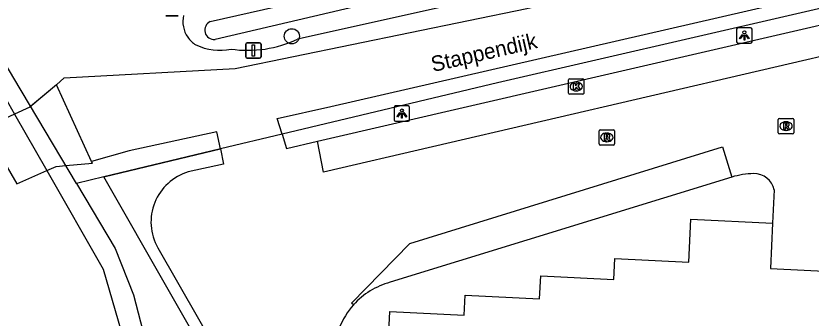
# Model space of a CAD drawing. Extents: x 161094 to 161705, y 379509 to 380907.
# Drawn here: x 161197.2 to 161248.7, y 379714.9 to 379734.5 of the extents above; entities that cross this region are included whole.
import ezdxf

# ---------------------------------------------------------------- set-up
doc = ezdxf.new("R2010")
doc.units = 0
for name, color, linetype in [('IMGEO_Afsluitpaal', 7, 'Continuous'), ('IMGEO_Boom', 7, 'Continuous'), ('IMGEO_Dek', 7, 'Continuous'), ('IMGEO_Fietspad_gesloten', 7, 'Continuous'), ('IMGEO_Groenvoorziening', 7, 'Continuous'), ('IMGEO_Hek', 7, 'Continuous'), ('IMGEO_Kolk', 7, 'Continuous'), ('IMGEO_Lichtpunt', 7, 'Continuous'), ('IMGEO_Openbare_ruimte_label', 7, 'Continuous'), ('IMGEO_Pand', 7, 'Continuous'), ('IMGEO_Parkeervlak_gesloten', 7, 'Continuous'), ('IMGEO_Rijbaan_lokaal_gesloten', 7, 'Continuous'), ('IMGEO_Rioolput', 7, 'Continuous'), ('IMGEO_Verkeersbordpaal', 7, 'Continuous'), ('IMGEO_Waterloop', 7, 'Continuous')]:
    doc.layers.add(name, color=color, linetype=linetype)

msp = doc.modelspace()

# ---------------------------------------------------------------- linework, layer by layer
at = {"layer": 'IMGEO_Afsluitpaal'}
for p, q in [((161207.736, 379734.468), (161206.946, 379734.468)), ((161206.946, 379734.468), (161207.736, 379734.468))]:
    msp.add_line(p, q, dxfattribs=at)
at = {"layer": 'IMGEO_Boom'}
msp.add_circle((161215.101, 379733.152), 0.489, dxfattribs=at)
at = {"layer": 'IMGEO_Dek'}
msp.add_lwpolyline([(161197.31, 379723.614), (161199.237, 379724.462), (161199.849, 379724.731), (161200.473, 379724.788), (161202.193, 379724.943), (161202.141, 379725.056), (161199.88, 379730.004), (161198.199, 379728.614), (161198.153, 379728.576), (161197.144, 379728.113), (161195.19, 379727.216)], close=True, dxfattribs=at)
at = {"layer": 'IMGEO_Fietspad_gesloten'}
for points in [[(161210.481, 379725.863), (161210.245, 379726.978), (161204.585, 379725.735), (161202.141, 379725.056), (161199.88, 379730.004), (161200.37, 379730.456), (161211.43, 379731.076), (161230.315, 379734.955), (161294.533, 379750), (161302.182, 379751.792), (161318.2, 379756.091), (161323.089, 379757.248), (161325.661, 379758.067), (161372.453, 379776.813), (161386.356, 379782.534), (161407.443, 379791.212), (161432.033, 379800.962), (161436.35, 379802.535), (161437.461, 379802.835), (161438.334, 379803.07)], [(161214.473, 379726.815), (161214.16, 379727.839), (161217.63, 379728.601), (161261.386, 379738.685), (161308.111, 379750), (161320.623, 379753.03), (161330.613, 379756.284), (161333.8, 379757.687), (161368.776, 379771.487), (161387.909, 379779.27), (161415.666, 379790.561)]]:
    msp.add_lwpolyline(points, dxfattribs=at)
at = {"layer": 'IMGEO_Groenvoorziening'}
for points in [[(161321.194, 379761.932), (161383.047, 379787.15), (161437.336, 379808.629), (161438.26, 379805.933), (161414.978, 379796.508), (161345.338, 379767.612), (161322.581, 379758.384), (161307.399, 379754.371), (161244.228, 379739.369), (161215.479, 379732.972)], [(161415.916, 379790.022), (161359.784, 379767.053), (161334.748, 379757.161), (161323.449, 379753.122), (161314.492, 379750.449), (161260.228, 379737.49), (161228.423, 379730.143), (161214.473, 379726.815)], [(161201.159, 379723.634), (161197.105, 379730.453), (161194.335, 379735.113), (161189.385, 379745.645), (161184.615, 379755.126), (161180.807, 379761.477)], [(161202.937, 379724.063), (161210.481, 379725.863)], [(161202.937, 379724.063), (161201.159, 379723.634)], [(161224.271, 379686.726), (161202.937, 379724.063)], [(161201.159, 379723.634), (161203.662, 379719.423), (161204.854, 379716.43), (161205.758, 379712.932), (161206.301, 379709.758), (161206.372, 379708.219)]]:
    msp.add_lwpolyline(points, dxfattribs=at)
for centre, radius, start, end in [((161209.849, 379734.112), 1.8, 167.4846, 214.3982), ((161209.848, 379734.116), 1.801, 214.5145, 237.8238), ((161210.452, 379736.058), 3.803, 245.735, 280.8512), ((161212.257, 379739.735), 7.491, 261.6448, 295.4778)]:
    msp.add_arc(centre, radius, start, end, dxfattribs=at)
at = {"layer": 'IMGEO_Hek'}
for points in [[(161415.916, 379790.022), (161359.784, 379767.053), (161334.748, 379757.161), (161323.449, 379753.122), (161314.492, 379750.449), (161260.228, 379737.49), (161228.423, 379730.143), (161214.473, 379726.815)], [(161199.88, 379730.004), (161198.153, 379728.576), (161197.144, 379728.113), (161195.19, 379727.216)], [(161214.473, 379726.815), (161210.481, 379725.863)], [(161210.481, 379725.863), (161202.937, 379724.063)], [(161197.31, 379723.614), (161199.237, 379724.462), (161199.849, 379724.731), (161200.473, 379724.788), (161202.193, 379724.943)], [(161224.271, 379686.726), (161202.937, 379724.063)]]:
    msp.add_lwpolyline(points, dxfattribs=at)
at = {"layer": 'IMGEO_Kolk'}
for p, q in [((161233.011, 379729.473), (161233.011, 379730.325)), ((161233.086, 379730.399), (161233.938, 379730.399)), ((161233.499, 379730.179), (161233.524, 379730.179)), ((161234.012, 379730.325), (161234.012, 379729.473)), ((161233.522, 379729.619), (161233.497, 379729.619)), ((161233.938, 379729.399), (161233.086, 379729.399))]:
    msp.add_line(p, q, dxfattribs=at)
for points in [[(161233.011, 379729.473), (161233.011, 379730.325)], [(161233.086, 379730.399), (161233.938, 379730.399)], [(161233.332, 379730.099), (161233.455, 379730.099), (161233.455, 379729.948), (161233.585, 379730.099), (161233.749, 379730.099), (161233.603, 379729.948), (161233.756, 379729.699), (161233.604, 379729.699), (161233.519, 379729.863), (161233.455, 379729.796), (161233.455, 379729.699), (161233.332, 379729.699), (161233.332, 379730.099)], [(161234.012, 379730.325), (161234.012, 379729.473)], [(161233.938, 379729.399), (161233.086, 379729.399)]]:
    msp.add_lwpolyline(points, dxfattribs=at)
for centre, start, end in [((161233.088, 379730.323), 91.552, 178.448), ((161233.088, 379730.323), 91.552, 178.448), ((161233.936, 379730.323), 1.552, 88.448), ((161233.936, 379730.323), 1.552, 88.448), ((161233.088, 379729.475), 181.552, 268.448), ((161233.088, 379729.475), 181.552, 268.448), ((161233.936, 379729.475), 271.552, 358.448), ((161233.936, 379729.475), 271.552, 358.448)]:
    msp.add_arc(centre, 0.0765, start, end, dxfattribs=at)
for centre, major_axis, ratio, start_param, end_param in [((161233.498, 379729.899), (-0.387, 0.002), 0.722429, 4.712389, 7.853982), ((161233.523, 379729.899), (-0.39, 0.002), 0.717154, 1.570796, 4.712389)]:
    msp.add_ellipse(centre, major_axis=major_axis, ratio=ratio, start_param=start_param, end_param=end_param, dxfattribs=at)
at = {"layer": 'IMGEO_Lichtpunt'}
for p, q in [((161243.893, 379733.61), (161243.893, 379732.803)), ((161243.893, 379733.61), (161243.893, 379732.803)), ((161244.795, 379733.705), (161243.987, 379733.705)), ((161244.795, 379733.705), (161243.987, 379733.705)), ((161244.889, 379732.803), (161244.889, 379733.61)), ((161244.889, 379732.803), (161244.889, 379733.61)), ((161243.987, 379732.709), (161244.795, 379732.709)), ((161243.987, 379732.709), (161244.795, 379732.709)), ((161221.727, 379728.553), (161221.727, 379727.746)), ((161221.727, 379728.553), (161221.727, 379727.746)), ((161222.629, 379728.648), (161221.821, 379728.648)), ((161222.629, 379728.648), (161221.821, 379728.648)), ((161222.723, 379727.746), (161222.723, 379728.553)), ((161222.723, 379727.746), (161222.723, 379728.553)), ((161221.821, 379727.652), (161222.629, 379727.652)), ((161221.821, 379727.652), (161222.629, 379727.652))]:
    msp.add_line(p, q, dxfattribs=at)
for points in [[(161244.267, 379733.274), (161244.306, 379733.246), (161244.118, 379732.984), (161244.08, 379733.011), (161244.267, 379733.274)], [(161244.369, 379733.226), (161244.416, 379733.226), (161244.416, 379732.904), (161244.369, 379732.904), (161244.369, 379733.226)], [(161244.479, 379733.246), (161244.517, 379733.273), (161244.704, 379733.011), (161244.665, 379732.983), (161244.479, 379733.246)], [(161222.101, 379728.217), (161222.14, 379728.189), (161221.952, 379727.927), (161221.914, 379727.954), (161222.101, 379728.217)], [(161222.203, 379728.169), (161222.25, 379728.169), (161222.25, 379727.847), (161222.203, 379727.847), (161222.203, 379728.169)], [(161222.313, 379728.189), (161222.351, 379728.216), (161222.538, 379727.954), (161222.499, 379727.926), (161222.313, 379728.189)]]:
    msp.add_lwpolyline(points, dxfattribs=at)
for centre in [(161244.392, 379733.408), (161222.226, 379728.351)]:
    msp.add_circle(centre, 0.0994, dxfattribs=at)
for centre, start, end in [((161243.987, 379733.61), 90, 180), ((161243.987, 379733.61), 90, 180), ((161244.795, 379733.61), 0, 90), ((161244.795, 379733.61), 0, 90), ((161243.987, 379732.803), 180, 270), ((161243.987, 379732.803), 180, 270), ((161244.795, 379732.803), 270, 0), ((161244.795, 379732.803), 270, 360), ((161221.821, 379728.553), 90, 180), ((161221.821, 379728.553), 90, 180), ((161222.629, 379728.553), 0, 90), ((161222.629, 379728.553), 0, 90), ((161221.821, 379727.746), 180, 270), ((161221.821, 379727.746), 180, 270), ((161222.629, 379727.746), 270, 0), ((161222.629, 379727.746), 270, 360)]:
    msp.add_arc(centre, 0.0946, start, end, dxfattribs=at)
at = {"layer": 'IMGEO_Pand'}
for points in [[(161246.219, 379721.063), (161246.076, 379718.139), (161250.433, 379717.926), (161250.668, 379722.709)], [(161221.202, 379710.583), (161221.435, 379715.343), (161226.263, 379715.106), (161226.326, 379716.404), (161231.137, 379716.169), (161231.21, 379717.664), (161235.949, 379717.432), (161236.015, 379718.779), (161240.798, 379718.545), (161240.934, 379721.322), (161246.219, 379721.063)]]:
    msp.add_lwpolyline(points, dxfattribs=at)
at = {"layer": 'IMGEO_Parkeervlak_gesloten'}
for points in [[(161216.77, 379726.358), (161281.548, 379741.341)], [(161243.578, 379724.047), (161221.468, 379717.239)]]:
    msp.add_lwpolyline(points, dxfattribs=at)
msp.add_arc((161222.749, 379712.493), 4.916, 105.1074, 138.0537, dxfattribs=at)
at = {"layer": 'IMGEO_Rijbaan_lokaal_gesloten'}
for points in [[(161281.548, 379741.341), (161281.952, 379739.475), (161252.424, 379732.547), (161217.161, 379724.368), (161216.77, 379726.358)], [(161214.473, 379726.815), (161210.481, 379725.863)], [(161214.473, 379726.815), (161214.755, 379725.892), (161216.77, 379726.358)], [(161210.481, 379725.863), (161210.689, 379724.879), (161208.4, 379724.379)], [(161219.093, 379715.779), (161218.965, 379715.895), (161222.736, 379719.759), (161242.968, 379725.996), (161243.578, 379724.047)], [(161246.325, 379723.213), (161246.219, 379721.063)], [(161206.424, 379719.47), (161218.401, 379698.575), (161236.659, 379665.622)]]:
    msp.add_lwpolyline(points, dxfattribs=at)
for centre, radius, start, end in [((161209.375, 379721.134), 3.388, 106.7284, 209.4194), ((161245.164, 379718.582), 5.691, 91.7141, 106.1855), ((161245.027, 379722.945), 1.326, 11.6765, 91.4146), ((161222.756, 379712.5), 4.917, 138.1622, 179.1438)]:
    msp.add_arc(centre, radius, start, end, dxfattribs=at)
at = {"layer": 'IMGEO_Rioolput'}
for p, q in [((161246.587, 379726.917), (161246.587, 379727.769)), ((161246.662, 379727.843), (161247.514, 379727.843)), ((161247.075, 379727.623), (161247.1, 379727.623)), ((161247.588, 379727.769), (161247.588, 379726.917)), ((161234.99, 379726.185), (161234.99, 379727.037)), ((161235.065, 379727.111), (161235.917, 379727.111)), ((161235.478, 379726.891), (161235.503, 379726.891)), ((161235.991, 379727.037), (161235.991, 379726.185)), ((161247.098, 379727.063), (161247.073, 379727.063)), ((161247.514, 379726.843), (161246.662, 379726.843)), ((161235.917, 379726.111), (161235.065, 379726.111)), ((161235.501, 379726.331), (161235.476, 379726.331))]:
    msp.add_line(p, q, dxfattribs=at)
for points in [[(161246.587, 379726.917), (161246.587, 379727.769)], [(161246.662, 379727.843), (161247.514, 379727.843)], [(161247.176, 379727.541), (161246.924, 379727.543), (161246.924, 379727.143)], [(161247.102, 379727.462), (161247.048, 379727.462), (161247.048, 379727.381)], [(161247.588, 379727.769), (161247.588, 379726.917)], [(161234.99, 379726.185), (161234.99, 379727.037)], [(161235.065, 379727.111), (161235.917, 379727.111)], [(161235.991, 379727.037), (161235.991, 379726.185)], [(161246.924, 379727.143), (161247.048, 379727.143), (161247.048, 379727.305), (161247.059, 379727.305)], [(161247.048, 379727.381), (161247.1, 379727.381)], [(161247.106, 379727.276), (161247.177, 379727.143), (161247.317, 379727.143), (161247.252, 379727.269)], [(161235.579, 379726.809), (161235.327, 379726.811), (161235.327, 379726.411)], [(161235.327, 379726.411), (161235.451, 379726.411), (161235.451, 379726.573), (161235.462, 379726.573)], [(161235.505, 379726.73), (161235.451, 379726.73), (161235.451, 379726.649)], [(161235.451, 379726.649), (161235.503, 379726.649)], [(161235.509, 379726.544), (161235.58, 379726.411), (161235.72, 379726.411), (161235.655, 379726.537)], [(161247.514, 379726.843), (161246.662, 379726.843)], [(161235.917, 379726.111), (161235.065, 379726.111)]]:
    msp.add_lwpolyline(points, dxfattribs=at)
for centre, radius, start, end in [((161246.664, 379727.767), 0.0765, 91.552, 178.448), ((161246.664, 379727.767), 0.0765, 91.552, 178.448), ((161247.084, 379727.57), 0.19, 274.7715, 282.9687), ((161247.108, 379727.366), 0.0964, 77.0061, 93.1865), ((161247.122, 379727.423), 0.0378, 276.6634, 79.6772), ((161247.175, 379727.431), 0.109, 350.3612, 89.416), ((161247.173, 379727.431), 0.112, 277.5842, 350.9817), ((161247.512, 379727.767), 0.0765, 1.552, 88.448), ((161247.512, 379727.767), 0.0765, 1.552, 88.448), ((161235.067, 379727.035), 0.0765, 91.552, 178.448), ((161235.067, 379727.035), 0.0765, 91.552, 178.448), ((161235.915, 379727.035), 0.0765, 1.552, 88.448), ((161235.915, 379727.035), 0.0765, 1.552, 88.448), ((161246.664, 379726.919), 0.0765, 181.552, 268.448), ((161246.664, 379726.919), 0.0765, 181.552, 268.448), ((161247.058, 379727.252), 0.0533, 26.0293, 88.6989), ((161247.157, 379727.216), 0.108, 29.5134, 73.7905), ((161247.512, 379726.919), 0.0765, 271.552, 358.448), ((161247.512, 379726.919), 0.0765, 271.552, 358.448), ((161235.461, 379726.52), 0.0533, 26.0293, 88.6989), ((161235.487, 379726.838), 0.19, 274.7715, 282.9687), ((161235.511, 379726.634), 0.0964, 77.0061, 93.1865), ((161235.525, 379726.691), 0.0378, 276.6634, 79.6772), ((161235.578, 379726.699), 0.109, 350.3612, 89.416), ((161235.576, 379726.699), 0.112, 277.5842, 350.9817), ((161235.56, 379726.484), 0.108, 29.5134, 73.7905), ((161235.067, 379726.187), 0.0765, 181.552, 268.448), ((161235.067, 379726.187), 0.0765, 181.552, 268.448), ((161235.915, 379726.187), 0.0765, 271.552, 358.448), ((161235.915, 379726.187), 0.0765, 271.552, 358.448)]:
    msp.add_arc(centre, radius, start, end, dxfattribs=at)
for centre, major_axis, ratio, start_param, end_param in [((161247.074, 379727.343), (-0.387, 0.002), 0.722429, 4.712389, 7.853982), ((161247.099, 379727.343), (-0.39, 0.002), 0.717154, 1.570796, 4.712389), ((161235.477, 379726.611), (-0.387, 0.002), 0.722429, 4.712389, 7.853982), ((161235.502, 379726.611), (-0.39, 0.002), 0.717154, 1.570796, 4.712389)]:
    msp.add_ellipse(centre, major_axis=major_axis, ratio=ratio, start_param=start_param, end_param=end_param, dxfattribs=at)
at = {"layer": 'IMGEO_Verkeersbordpaal'}
for p, q in [((161212.118, 379731.831), (161212.118, 379732.631)), ((161212.118, 379732.631), (161212.118, 379731.831)), ((161212.218, 379732.731), (161213.008, 379732.731)), ((161213.008, 379732.731), (161212.218, 379732.731)), ((161213.108, 379732.631), (161213.108, 379731.831)), ((161213.108, 379731.831), (161213.108, 379732.631)), ((161213.008, 379731.731), (161212.218, 379731.731)), ((161212.218, 379731.731), (161213.008, 379731.731))]:
    msp.add_line(p, q, dxfattribs=at)
msp.add_lwpolyline([(161212.538, 379732.606), (161212.688, 379732.606), (161212.688, 379731.856), (161212.538, 379731.856), (161212.538, 379732.606)], dxfattribs=at)
for centre, start, end in [((161212.218, 379732.631), 90, 180), ((161212.218, 379732.631), 90, 180), ((161213.008, 379732.631), 0, 90), ((161213.008, 379732.631), 360, 90), ((161212.218, 379731.831), 180, 270), ((161212.218, 379731.831), 180, 270), ((161213.008, 379731.831), 270, 0), ((161213.008, 379731.831), 270, 0)]:
    msp.add_arc(centre, 0.1, start, end, dxfattribs=at)
at = {"layer": 'IMGEO_Waterloop'}
for points in [[(161209.828, 379734.106), (161253.524, 379743.962), (161280.711, 379750.533), (161313.565, 379758.418), (161319.274, 379759.897), (161322.067, 379760.718), (161345.722, 379770.082), (161377.919, 379783.264), (161415.988, 379798.829), (161436.933, 379807.33), (161437.303, 379806.344), (161408.802, 379795.092), (161371.225, 379779.322), (161334.181, 379764.414), (161322.108, 379759.712), (161320.444, 379759.342), (161312.949, 379757.494), (161293.093, 379752.607), (161257.077, 379743.942), (161210.131, 379732.941)], [(161181.414, 379758.547), (161186.34, 379750), (161193.314, 379734.795), (161195.957, 379730.183), (161197.144, 379728.113), (161199.237, 379724.462), (161202.883, 379718.1), (161204.245, 379713.411), (161204.369, 379711.621)]]:
    msp.add_lwpolyline(points, dxfattribs=at)
msp.add_arc((161210.08, 379733.55), 0.611, 114.3313, 274.8264, dxfattribs=at)

# ---------------------------------------------------------------- texts
at = {"layer": 'IMGEO_Openbare_ruimte_label'}
msp.add_text('Stappendijk', height=1, rotation=13.0075, dxfattribs=at).set_placement((161224.241, 379730.835))

doc.saveas('drawing.dxf')
